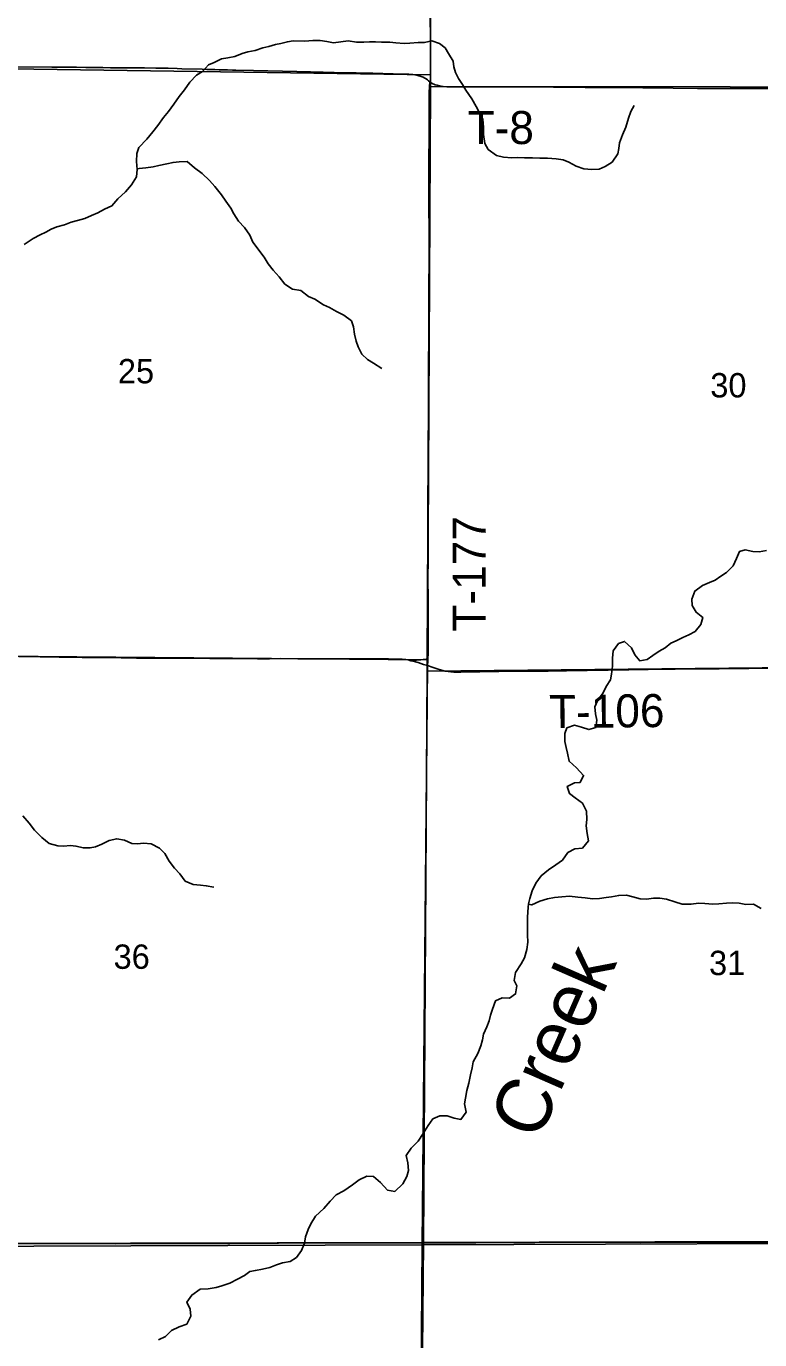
# Model space of a CAD drawing. Extents: x 0 to 34, y 0 to 22.
# Drawn here: x 8.152 to 8.783, y 17.325 to 18.454 of the extents above; entities that cross this region are included whole.
import ezdxf

# ---------------------------------------------------------------- set-up
doc = ezdxf.new("R2010")
doc.units = 0
for name, color, linetype in [('GM_X_County_Road', 7, 'Continuous'), ('GM_X_Minor_River', 7, 'Continuous'), ('GM_X_Minor_River_Text', 7, 'Continuous'), ('GM_X_Section', 7, 'Continuous'), ('GM_X_Section_Text', 7, 'Continuous'), ('GM_X_Township', 7, 'Continuous'), ('GM_X_Township_Road', 7, 'Continuous'), ('GM_X_Township_Road_Text', 7, 'Continuous'), ('GM_X_US_Route', 7, 'Continuous')]:
    doc.layers.add(name, color=color, linetype=linetype)

msp = doc.modelspace()

# ---------------------------------------------------------------- linework, layer by layer
at = {"layer": 'GM_X_County_Road'}
for points in [[(8.1424, 18.419), (8.1744, 18.4188), (8.1878, 18.4188), (8.1955, 18.4187), (8.2036, 18.4185), (8.2054, 18.4185), (8.2182, 18.4183), (8.2247, 18.4181), (8.2374, 18.4181), (8.2412, 18.418), (8.244, 18.418), (8.254, 18.418), (8.2638, 18.4178), (8.2744, 18.4177), (8.2821, 18.4175), (8.2862, 18.4174), (8.3036, 18.417), (8.3076, 18.4168), (8.3144, 18.4166), (8.3182, 18.4165), (8.3253, 18.4163), (8.3297, 18.4162), (8.3325, 18.4161), (8.3477, 18.4159), (8.385, 18.4151), (8.3968, 18.4147), (8.4077, 18.4145), (8.417, 18.4142), (8.4359, 18.4138), (8.4412, 18.4136), (8.4465, 18.4135), (8.4502, 18.4134), (8.4589, 18.4132), (8.477, 18.4128), (8.4794, 18.4127), (8.4813, 18.4126), (8.4847, 18.4123), (8.488, 18.4117), (8.4897, 18.4113), (8.4909, 18.4109), (8.4934, 18.41), (8.495, 18.4092), (8.496, 18.4086), (8.4972, 18.4078), (8.4982, 18.407), (8.4992, 18.406)], [(8.1272, 17.9124), (8.1642, 17.9118), (8.1806, 17.9115), (8.2005, 17.9112), (8.2207, 17.9111), (8.2471, 17.9108), (8.2801, 17.9106), (8.3102, 17.9104), (8.3261, 17.9105), (8.3298, 17.9104), (8.3348, 17.9104), (8.3422, 17.9103), (8.3512, 17.9102), (8.3615, 17.9102), (8.3711, 17.9103), (8.3857, 17.9102), (8.4016, 17.9102), (8.4252, 17.9101), (8.4364, 17.91), (8.4442, 17.91), (8.4566, 17.91), (8.4637, 17.91), (8.4715, 17.9099), (8.4756, 17.9097), (8.4771, 17.9096), (8.4786, 17.9094), (8.4806, 17.9091), (8.4829, 17.9085)], [(8.4829, 17.9085), (8.4839, 17.9083), (8.4893, 17.9068), (8.4939, 17.9053), (8.4973, 17.9043)]]:
    msp.add_lwpolyline(points, dxfattribs=at)
at = {"layer": 'GM_X_Minor_River'}
for points in [[(8.2138, 18.2935), (8.2197, 18.2965), (8.226, 18.2995), (8.231, 18.3054), (8.2376, 18.3114), (8.2428, 18.3175), (8.247, 18.3243), (8.2478, 18.3307), (8.2472, 18.3375), (8.2473, 18.3444), (8.249, 18.3495), (8.256, 18.3569), (8.2612, 18.3631), (8.2654, 18.3686), (8.2703, 18.3754), (8.2747, 18.3807), (8.2791, 18.3869), (8.2839, 18.3934), (8.2883, 18.3991), (8.2931, 18.4057), (8.2988, 18.4117), (8.3039, 18.4149), (8.3089, 18.4206), (8.314, 18.4227), (8.3201, 18.4259), (8.3256, 18.4266), (8.3317, 18.4279), (8.338, 18.4304), (8.3429, 18.4318), (8.3492, 18.433), (8.3556, 18.4352), (8.3609, 18.4365), (8.3665, 18.4382), (8.3712, 18.4391), (8.3769, 18.4406), (8.3817, 18.4412), (8.3919, 18.4411), (8.3987, 18.4417), (8.405, 18.4415), (8.4107, 18.4407), (8.4164, 18.4397), (8.4228, 18.4404), (8.4291, 18.4414), (8.4363, 18.4402), (8.4424, 18.4403), (8.4475, 18.4405), (8.4524, 18.4405), (8.4578, 18.4401), (8.4648, 18.4403), (8.4701, 18.4397), (8.4773, 18.4391), (8.4821, 18.4392), (8.4893, 18.44), (8.4946, 18.4399), (8.5009, 18.4412), (8.5075, 18.4391), (8.5124, 18.4353), (8.5154, 18.4304), (8.5192, 18.4239), (8.5199, 18.419), (8.5214, 18.414), (8.5239, 18.4091), (8.5273, 18.4037), (8.5301, 18.3988), (8.5354, 18.3914), (8.5391, 18.3849), (8.5416, 18.3801), (8.5448, 18.3739), (8.5453, 18.3672), (8.5455, 18.3608), (8.5466, 18.3532), (8.5494, 18.348), (8.5566, 18.3427), (8.5627, 18.3413), (8.5697, 18.3407), (8.5748, 18.3411), (8.5807, 18.3409), (8.5875, 18.3409), (8.5938, 18.3405), (8.6003, 18.3404), (8.6077, 18.3398), (8.6137, 18.3389), (8.6187, 18.3369), (8.6251, 18.3337), (8.6315, 18.3314), (8.6384, 18.3306), (8.6448, 18.3311), (8.6498, 18.3334), (8.6559, 18.337), (8.6608, 18.3442), (8.6618, 18.3489), (8.6622, 18.3536), (8.6647, 18.3605), (8.6676, 18.3671), (8.6701, 18.3749), (8.672, 18.3807), (8.675, 18.3857)], [(8.2477, 18.3313), (8.2493, 18.3315), (8.2552, 18.3322), (8.2613, 18.3331), (8.2662, 18.3341), (8.2732, 18.3357), (8.2785, 18.3368), (8.2839, 18.3374), (8.2907, 18.3376), (8.2971, 18.3322), (8.3036, 18.3273), (8.31, 18.3212), (8.3145, 18.316), (8.3202, 18.309), (8.3238, 18.3036), (8.3281, 18.2974), (8.3309, 18.2926), (8.3347, 18.2863), (8.34, 18.281), (8.3445, 18.2743), (8.347, 18.2684), (8.3568, 18.2555), (8.3602, 18.2496), (8.3645, 18.2441), (8.3698, 18.2385), (8.3747, 18.2323), (8.3811, 18.2279), (8.3885, 18.2267), (8.395, 18.2217), (8.4003, 18.2192), (8.4078, 18.2145), (8.413, 18.212), (8.419, 18.2087), (8.4253, 18.2055), (8.4319, 18.2005), (8.4336, 18.1954), (8.4345, 18.1893), (8.436, 18.1832), (8.4377, 18.1783), (8.4407, 18.172), (8.4458, 18.1674), (8.4509, 18.1642), (8.4581, 18.1598)], [(8.1507, 18.2664), (8.1583, 18.2713), (8.1644, 18.2745), (8.1692, 18.2768), (8.1739, 18.2794), (8.1787, 18.2815), (8.1851, 18.2833), (8.191, 18.2854), (8.1965, 18.2869), (8.2028, 18.2886), (8.2085, 18.2912), (8.2138, 18.2935)], [(8.617, 17.8507), (8.6235, 17.853), (8.6295, 17.8514), (8.636, 17.8493), (8.642, 17.8512), (8.6428, 17.8574), (8.6415, 17.8628), (8.6412, 17.8688), (8.6437, 17.8745), (8.6482, 17.881), (8.6507, 17.8863), (8.6544, 17.8919), (8.6555, 17.8969), (8.6563, 17.9037), (8.6562, 17.9107), (8.6569, 17.917), (8.6615, 17.9232), (8.6667, 17.9251), (8.6727, 17.9196), (8.6755, 17.9135), (8.6797, 17.9085), (8.6859, 17.9095), (8.6909, 17.913), (8.6964, 17.9166), (8.7015, 17.9194), (8.7063, 17.9236), (8.7111, 17.9257), (8.7168, 17.9285), (8.7219, 17.9307), (8.7274, 17.9336), (8.7322, 17.9396), (8.7339, 17.9457), (8.7283, 17.9501), (8.7247, 17.9558), (8.7245, 17.9615), (8.727, 17.9683), (8.7335, 17.9732), (8.7397, 17.9756), (8.7445, 17.9777), (8.7494, 17.9811), (8.7542, 17.9843), (8.7599, 17.99), (8.7628, 17.9964), (8.7653, 18.0023), (8.7702, 18.0038), (8.7769, 18.0023), (8.7822, 18.002), (8.7885, 18.0033)], [(8.34, 17.3801), (8.3444, 17.3835), (8.3493, 17.3844), (8.3554, 17.3854), (8.3616, 17.3869), (8.3675, 17.3891), (8.3725, 17.391), (8.3791, 17.3921), (8.3845, 17.3955), (8.389, 17.4015), (8.3915, 17.4078), (8.3925, 17.4131), (8.3946, 17.4194), (8.3969, 17.4243), (8.4011, 17.4309), (8.408, 17.4377), (8.4137, 17.444), (8.4187, 17.4492), (8.4253, 17.4528), (8.4327, 17.4579), (8.4386, 17.4621), (8.4451, 17.4655), (8.4508, 17.465), (8.4567, 17.4599), (8.4629, 17.4532), (8.4692, 17.4523), (8.476, 17.4587), (8.4795, 17.4651), (8.4808, 17.4702), (8.4803, 17.4767), (8.479, 17.483), (8.4832, 17.4894), (8.4893, 17.4956), (8.4935, 17.5021), (8.4977, 17.5089), (8.5019, 17.5147), (8.5078, 17.5172), (8.5142, 17.5172), (8.5201, 17.5152), (8.526, 17.5141), (8.5304, 17.5205), (8.5291, 17.5275), (8.5299, 17.5325), (8.531, 17.5389), (8.5328, 17.5452), (8.5343, 17.5524), (8.5355, 17.5586), (8.5366, 17.5636), (8.5405, 17.5708), (8.543, 17.5774), (8.5445, 17.5827), (8.5455, 17.5874), (8.5481, 17.5937), (8.5503, 17.599), (8.5514, 17.6037), (8.553, 17.609), (8.5556, 17.616), (8.5613, 17.6187), (8.5678, 17.6185), (8.5729, 17.622), (8.5741, 17.6289), (8.5718, 17.6336), (8.5728, 17.6405), (8.5778, 17.6478), (8.5805, 17.6531), (8.5826, 17.6603), (8.5836, 17.6664), (8.5832, 17.6729), (8.5833, 17.6823), (8.5831, 17.6875), (8.5835, 17.693), (8.5841, 17.6994), (8.5851, 17.7042), (8.5872, 17.7106), (8.5904, 17.7172), (8.5948, 17.7235), (8.6011, 17.7288), (8.6074, 17.7329), (8.6133, 17.7371), (8.6179, 17.7435), (8.6238, 17.7469), (8.6304, 17.7472), (8.6357, 17.7535), (8.6346, 17.7599), (8.6335, 17.7666), (8.6341, 17.7721), (8.6338, 17.7791), (8.6306, 17.786), (8.6243, 17.7907), (8.6194, 17.7943), (8.6173, 17.8004), (8.6236, 17.8034), (8.6284, 17.8038), (8.6314, 17.8099), (8.6254, 17.8163), (8.619, 17.8221), (8.6177, 17.8289), (8.6163, 17.8338), (8.6152, 17.839), (8.6154, 17.8458), (8.617, 17.8507)], [(8.1494, 17.7751), (8.1549, 17.7688), (8.1594, 17.7629), (8.1658, 17.7566), (8.1721, 17.7513), (8.1795, 17.7493), (8.1844, 17.7491), (8.1903, 17.7497), (8.195, 17.7491), (8.2015, 17.7475), (8.2072, 17.7475), (8.2119, 17.7484), (8.2174, 17.7509), (8.2237, 17.7539), (8.2302, 17.7554), (8.2368, 17.7542), (8.2431, 17.7513), (8.248, 17.7511), (8.2531, 17.7515), (8.2596, 17.7511), (8.267, 17.7474), (8.2715, 17.7427), (8.2753, 17.7362), (8.2798, 17.7301), (8.2843, 17.7254), (8.289, 17.7191), (8.2957, 17.716), (8.3021, 17.7154), (8.3071, 17.715), (8.3135, 17.7138)], [(8.5841, 17.6991), (8.5869, 17.6985), (8.5938, 17.7017), (8.6004, 17.7037), (8.6063, 17.7048), (8.6126, 17.7054), (8.6194, 17.7061), (8.6264, 17.7053), (8.6327, 17.7045), (8.6391, 17.7039), (8.645, 17.7041), (8.6507, 17.705), (8.6555, 17.7056), (8.6616, 17.7067), (8.6684, 17.707), (8.6737, 17.7055), (8.6801, 17.7038), (8.6855, 17.7035), (8.6915, 17.7043), (8.697, 17.7043), (8.7027, 17.7035), (8.7099, 17.7012), (8.7162, 17.6991), (8.7238, 17.6992), (8.7302, 17.7001), (8.7355, 17.6999), (8.7426, 17.6993), (8.7475, 17.6995), (8.7543, 17.7), (8.7598, 17.7004), (8.765, 17.7), (8.7708, 17.699), (8.7775, 17.6992), (8.7841, 17.6954)], [(8.2659, 17.3246), (8.272, 17.3275), (8.2771, 17.3326), (8.2838, 17.3358), (8.2903, 17.3382), (8.2937, 17.345), (8.2932, 17.3509), (8.2905, 17.3572), (8.2946, 17.3632), (8.3018, 17.3681), (8.3086, 17.3685), (8.3155, 17.3698), (8.3206, 17.3711), (8.3274, 17.3735), (8.3339, 17.3769), (8.34, 17.3801)]]:
    msp.add_lwpolyline(points, dxfattribs=at)
at = {"layer": 'GM_X_Section'}
for points in [[(7.9931, 18.9255), (8.4977, 18.9139), (8.4981, 18.9029), (8.4999, 18.4122), (7.9982, 18.4192)], [(8.4981, 18.9029), (9.0213, 18.9032), (9.0152, 18.4014), (8.4994, 18.4021), (8.4999, 18.4122)], [(7.9982, 18.4192), (8.4999, 18.4122), (8.4994, 18.4021), (8.4969, 17.9091), (7.995, 17.9135)], [(8.4994, 18.4021), (9.0152, 18.4014), (9.0151, 17.9046), (8.4969, 17.8994), (8.4969, 17.9091)], [(7.995, 17.9135), (8.4969, 17.9091), (8.4969, 17.8994), (8.4938, 17.4083), (7.9898, 17.4073)], [(8.4969, 17.8994), (9.0151, 17.9046), (9.0162, 17.4099), (8.9908, 17.4098), (8.4938, 17.4083)], [(7.9898, 17.4073), (8.4938, 17.4083), (8.4891, 16.9146), (7.9678, 16.9067), (7.976, 17.4076)], [(8.4938, 17.4083), (8.9908, 17.4098), (8.9931, 16.916), (8.4891, 16.9146)]]:
    msp.add_lwpolyline(points, close=True, dxfattribs=at)
at = {"layer": 'GM_X_Township'}
for points in [[(6.7822, 20.4149), (7.0235, 20.4144), (7.0997, 20.4161), (7.185, 20.4133), (7.2017, 20.4135), (7.3295, 20.4133), (7.7457, 20.4181), (7.8262, 20.4215), (7.9753, 20.4265), (8.5011, 20.4527), (8.493, 20.1675), (8.4861, 19.9159), (8.486, 19.9121), (8.4932, 19.4121), (8.4993, 18.91), (8.4999, 18.4019), (8.4971, 17.9043), (8.4927, 17.4064), (7.9915, 17.4046), (7.9762, 17.4045), (7.486, 17.4058), (7.4791, 17.4058), (6.9784, 17.4112), (6.8511, 17.4114)], [(9.4, 20.4572), (9.0515, 20.4584), (9.0372, 20.4584), (8.5011, 20.4527), (8.493, 20.1675), (8.4861, 19.9159), (8.486, 19.9121), (8.4932, 19.4121), (8.4993, 18.91), (8.4999, 18.4019), (8.4971, 17.9043), (8.4927, 17.4064), (8.965, 17.4081), (8.9926, 17.4083), (9.4, 17.4092)], [(5.4581, 16.8564), (5.4635, 17.412), (5.8548, 17.4123), (6.2198, 17.4124), (6.416, 17.4127), (6.7459, 17.4108), (6.8511, 17.4114), (6.9784, 17.4112), (7.4791, 17.4058), (7.486, 17.4058), (7.9762, 17.4045), (7.9915, 17.4046), (8.4927, 17.4064), (8.489, 16.9129)], [(9.4, 17.4092), (8.9926, 17.4083), (8.965, 17.4081), (8.4927, 17.4064), (8.489, 16.9129), (8.4875, 16.7165), (8.4852, 16.414), (8.4805, 15.9065), (8.4802, 15.8707), (8.4804, 15.8413), (8.4727, 15.4034), (8.4648, 14.9001), (8.4648, 14.8948), (8.4627, 14.3996), (8.961, 14.3984), (8.9649, 14.3985), (9.4, 14.3965)]]:
    msp.add_lwpolyline(points, dxfattribs=at)
at = {"layer": 'GM_X_Township_Road'}
for points in [[(8.4976, 17.9101), (8.4978, 17.9151), (8.4979, 17.9272), (8.4978, 17.9614), (8.4976, 17.9791), (8.4975, 18.0031), (8.4974, 18.0323), (8.4978, 18.086), (8.498, 18.127), (8.4981, 18.1556), (8.4983, 18.1935), (8.4984, 18.215), (8.4986, 18.2675), (8.4985, 18.3101), (8.4985, 18.3318), (8.4986, 18.3654), (8.4987, 18.3936), (8.4988, 18.3972), (8.4992, 18.406)], [(8.4992, 18.406), (8.5004, 18.4052), (8.5019, 18.4044), (8.5027, 18.404), (8.5038, 18.4036), (8.5055, 18.4031), (8.5075, 18.4026), (8.5089, 18.4024), (8.5108, 18.4022), (8.5138, 18.4019), (8.5165, 18.4019), (8.533, 18.4018), (8.5544, 18.4018), (8.5799, 18.4017), (8.6054, 18.4014), (8.6327, 18.4012), (8.6822, 18.4008), (8.7083, 18.4007), (8.7294, 18.4005), (8.7571, 18.4004), (8.8003, 18.4003)], [(8.4829, 17.9085), (8.4879, 17.9089), (8.4901, 17.9091), (8.4916, 17.9092), (8.4934, 17.9095), (8.4962, 17.9099), (8.4976, 17.9101)], [(8.4973, 17.9043), (8.4975, 17.9081), (8.4976, 17.9101)], [(8.4973, 17.9043), (8.5021, 17.9027), (8.5047, 17.9018), (8.5065, 17.9012), (8.5084, 17.9006), (8.5105, 17.9001), (8.5125, 17.8996), (8.5151, 17.8991), (8.5174, 17.8988), (8.5199, 17.8986), (8.526, 17.8987), (8.5586, 17.8991), (8.5813, 17.8994), (8.6009, 17.8996), (8.6167, 17.8998), (8.6702, 17.9006), (8.6869, 17.9008), (8.7332, 17.9014), (8.7479, 17.9016), (8.7991, 17.9021)]]:
    msp.add_lwpolyline(points, dxfattribs=at)
at = {"layer": 'GM_X_US_Route'}
msp.add_lwpolyline([(8.1271, 17.4073), (8.1712, 17.4074), (8.2104, 17.4074), (8.229, 17.4073), (8.2685, 17.4075), (8.2815, 17.4075), (8.298, 17.4075), (8.3272, 17.4075), (8.3692, 17.4078), (8.4142, 17.408), (8.4801, 17.4082), (8.4907, 17.4082), (8.4943, 17.4082), (8.5068, 17.4082), (8.5193, 17.4082), (8.5388, 17.4082), (8.5621, 17.4084), (8.5895, 17.4084), (8.6087, 17.4085), (8.6494, 17.4085), (8.6805, 17.4084), (8.715, 17.4086), (8.7427, 17.4086), (8.7573, 17.4085), (8.7703, 17.4086), (8.7943, 17.4086)], dxfattribs=at)

# ---------------------------------------------------------------- texts
at = {"layer": 'GM_X_Minor_River_Text'}
msp.add_text('Creek', height=0.04737, rotation=66.3438, dxfattribs=at).set_placement((8.5926, 17.4945))
at = {"layer": 'GM_X_Section_Text'}
for s, p in [('25', (8.2311, 18.1469)), ('30', (8.7403, 18.1348)), ('36', (8.2274, 17.6436)), ('31', (8.7392, 17.6382))]:
    msp.add_text(s, height=0.02093, rotation=0, dxfattribs=at).set_placement(p)
at = {"layer": 'GM_X_Township_Road_Text'}
for s, rotation, p in [('T-8', 0, (8.5317, 18.3526)), ('T-177', 90, (8.5473, 17.9335)), ('T-106', 0.5603, (8.6018, 17.8505))]:
    msp.add_text(s, height=0.02841, rotation=rotation, dxfattribs=at).set_placement(p)

doc.saveas('drawing.dxf')
